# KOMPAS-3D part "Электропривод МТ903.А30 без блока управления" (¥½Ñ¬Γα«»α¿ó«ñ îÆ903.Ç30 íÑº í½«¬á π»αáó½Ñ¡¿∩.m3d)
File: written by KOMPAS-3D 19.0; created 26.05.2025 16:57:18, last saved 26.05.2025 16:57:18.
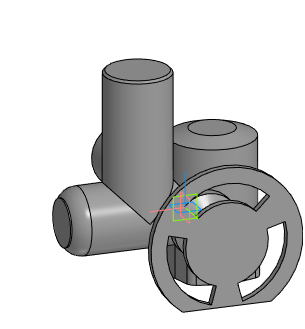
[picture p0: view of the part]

Document properties: Полное имя файла: E:\Dendor Работа Сачек\3D для проекитирвщиков\3.4 Электропривод МТ903.А\stp_Тип МТ903.А без блока управления\Электропривод МТ903.А30 без блока управления.m3d

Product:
- Part/product: Электропривод МТ903.А30 без блока управления

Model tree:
1. Операция без истории:1  (labels: Электропривод МТ903.А30 без блока управления)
